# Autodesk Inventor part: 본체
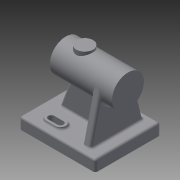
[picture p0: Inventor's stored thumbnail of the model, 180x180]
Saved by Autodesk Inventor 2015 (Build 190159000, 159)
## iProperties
Created: 2022-06
Part Number: 본체
Material: 일반
Document SubType Name: Modeling
Designer: 104589
Density: 1 g/cm^3
Appearance: 기본값
Author: 104589
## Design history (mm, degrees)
sketch "스케치1"
  geometry: L1 (50, -43)-(-50, -43); L2 (-50, -43)-(-50, 43); L3 (-50, 43)-(50, 43); L4 (50, 43)-(50, -43); L5 (50, -43)-(-50, 43); L6 (-50, -43)-(50, 43); 1 further point
  constraints: 12 end point, 2 midpoint, 2 parallel, 1 horizontal, 1 perpendicular
  dimensions: "d0" = 100 distance of L1.start L1.end; "d1" = 86 distance of L1.end L2.end
extrude "돌출1" new body sketch "스케치1" distance "d2" = 15; taper "d3" = 0 deg
sketch "스케치2"
  geometry: L1 (-50, 43)-(-50, -43) reference; L2 (-24, 27)-(-12, 27); L3 (-24, 20)-(-12, 20); L4 (-12, 34)-(-24, 34); A1 r 7 centre (-24, 27) between (-24, 34) and (-24, 20); A2 r 7 centre (-12, 27) between (-12, 20) and (-12, 34); 2 further points
  constraints: 8 end point, 4 point on circle, 4 tangent, 2 centre point, 1 horizontal, 1 midpoint, 1 parallel
  dimensions: "d4" = 26 distance from line of L1 L2.start; "d5" = 12 distance of L2.end L2.start; "d6" = 27 vertical distance of point (0, 0) point (-18, 27); "d7" = 14 distance between parallel lines of L3 L4
extrude "돌출2" join sketch "스케치2" distance "d8" = 3; taper "d9" = 0 deg
sketch "스케치3"
  geometry: L1 (-24, 20)-(-12, 20) reference; L2 (-12, 34)-(-24, 34) reference; L3 (-24, 31)-(-12, 31); L4 (-12, 23)-(-24, 23); A1 r 7 centre (-12, 27) between (-12, 20) and (-12, 34) reference; A2 r 7 centre (-24, 27) between (-24, 34) and (-24, 20) reference; A3 r 4 centre (-12, 27) between (-12, 23) and (-12, 31); A4 r 4 centre (-24, 27) between (-24, 31) and (-24, 23); 1 further point
  constraints: 4 end point, 4 point on circle, 2 centre point, 3 other
  dimensions: "d10" = 8 distance between parallel lines of L3 L4
extrude "돌출3" cut sketch "스케치3" stored distance "d11" = 3; taper "d12" = 0 deg
fillet "모깎기1" dims "d13" = 3
sketch "스케치4"
  geometry: L1 (-50, -43)-(50, -43) reference; L2 (50, -43)-(50, 43) reference; L3 (-50, 43)-(-50, -43) reference; L4 (-35, -5)-(35, -5); L5 (35, -5)-(35, 5); L6 (35, 5)-(-35, 5); L7 (-35, 5)-(-35, -5); L8 (-35, -5)-(35, 5); L9 (35, -5)-(-35, 5); 1 further point
  constraints: 12 end point, 2 midpoint, 2 parallel, 1 horizontal, 1 perpendicular
  dimensions: "d14" = 15 distance between parallel lines of L2 L5; "d15" = 15 distance between parallel lines of L3 L7 (derived); "d16" = 10 distance between parallel lines of L4 L6; "d17" = 43 distance from line of L1 point (0, 0) (derived)
extrude "돌출4" join sketch "스케치4" distance "d18" = 57; taper "d19" = 0 deg
feature "면 기울기1" dims angle "d20" = 20 deg
node "작업 평면1"
sketch "스케치5"
  geometry: L1 (-15, 38)-(-72, 38) reference; L2 (-72, 38)-(-72, 48) reference; L3 (-72, 48)-(-15, 48) reference; L4 (-15, 38)-(-15, 48) reference; L5 (-15, 0)-(-15, 38) reference; L6 (0, 0)-(-15, 0) reference; L7 (0, 86)-(0, 0) reference; L8 (-15, 86)-(0, 86) reference; L9 (-15, 48)-(-15, 86) reference; L10 (-76.814, 22.559)-(-15, 8); L11 (-76.814, 63.441)-(-15, 78); L12 (-76.814, 22.559)-(-76.814, 63.441); L13 (-15, 8)-(-15, 78); L14 (-15, 80)-(-15, 60) reference; A1 r 21 centre (-72, 43) between (-76.814, 22.559) and (-76.814, 63.441); 1 further point
  constraints: 8 end point, 2 point on circle, 2 point on line, 1 centre point, 1 collinear, 1 midpoint, 1 tangent, 1 vertical
  dimensions: "d22" = 42 diameter of A1; "d23" = 8 distance from line of L8 L11.end; "d24" = 8 distance of L10.end L5.start
extrude "돌출5" join sketch "스케치5" distance "d25" = 10; taper "d26" = 0 deg
fillet "모깎기2" dims "d27" = 3
fillet "모깎기3" dims "d28" = 3
fillet "모깎기4" dims "d29" = 3
sketch "스케치6"
  geometry: L1 (-35, 76.814)-(-25, 76.814) reference; L2 (-25, 76.814)-(-25, 72) reference; L3 (-25, 72)-(14.254, 72) reference; L4 (14.254, 72)-(35, 15) reference; L5 (35, 15)-(47, 15) reference; L6 (50, 12)-(50, 0) reference; L7 (50, 0)-(-50, 0) reference; L8 (-50, 0)-(-50, 12) reference; L9 (-47, 15)-(-35, 15) reference; L10 (-35, 15)-(-35, 76.814) reference; L11 (32, 93)-(-50, 93); L12 (-50, 93)-(-50, 72); L13 (-50, 72)-(32, 72); L14 (32, 72)-(32, 93); A1 r 3 centre (47, 12) between (50, 12) and (47, 15) reference; A2 r 3 centre (-47, 12) between (-47, 15) and (-50, 12) reference; 1 further point
  constraints: 8 end point, 2 collinear, 2 parallel, 1 horizontal, 1 perpendicular
  dimensions: "d30" = 72 distance between parallel lines of L7 L3 (derived); "d32" = 82 distance of L11.start L11.end; "d33" = 21 distance of L11.end L12.end
revolve "회전1" sketch "스케치6" stored, may be unused: angle "d34" = 90 deg
fillet "모깎기5" dims "d35" = 3
node "작업 평면2"
sketch "스케치7"
  geometry: L1 (-50, -21)-(-50, 21) reference; L2 (32, -21)-(32, 21) reference; L3 (-38, 18.515)-(-38, -18.515) reference; L4 (-32, 20.441)-(-28, 20.441) reference; L5 (-22, 7)-(-22, 18.515) reference; L6 (19.297, 7)-(-22, 7) reference; L7 (-22, -7)-(19.297, -7) reference; L8 (-22, -18.515)-(-22, -7) reference; L9 (-32, -20.441)-(-28, -20.441) reference; L10 (-50, 21)-(32, 21) reference; L11 (-50, -21)-(32, -21) reference; C1 r 11 at (7, 0); 4 further points; 1 other entity
  constraints: 1 centre point, 1 horizontal alignment, 7 other
  dimensions: "d37" = 22 diameter of C1; "d38" = 25 distance from line of C1.centre L2
extrude "돌출6" join sketch "스케치7" stored distance "d39" = 10; taper "d40" = 0 deg
fillet "모깎기6" dims "d41" = 3
node "솔리드1"
mirror "대칭1"
node "투영된 루프1"
node "절단 모서리 투영1"
node "절단 모서리 투영2"
other parameters: "d21" = -15, "d36" = -96
